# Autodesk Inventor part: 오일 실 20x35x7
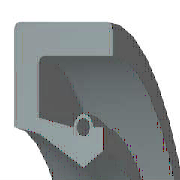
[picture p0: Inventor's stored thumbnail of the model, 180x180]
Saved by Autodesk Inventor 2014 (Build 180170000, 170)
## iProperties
IsCustomPart: 1
Created: 2012-02
Part Number: 오일 실 20x35x7
Material: 고무
Description: 회전 샤프트 립 유형 실 2 - 금속 케이스
Document SubType Name: Modeling
Standard: ISO 6194/1
Designer: mduedu
Standards Organization: ISO
Language: ko-KR
Size Designation: 20x35x7-유형 2
Categories: <MemberInstance><Categories><Category DisplayName="샤프트 부품" InternalName="7f7aeb1f-a693-4053-b835-cee3144e0d98" Mnemonic="SHFT"><Category DisplayName="실링" Intern
Density: 0.93 g/cm^3
Appearance: 고무 - 검은색 - 버전 1.1
Author: mduedu
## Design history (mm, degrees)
node "WorkPlane2"
node "WorkPoint1"
node "WorkPlane3"
body "Solid1"
node "스케치1"
revolve "회전1" stored, may be unused: angle "d37" = 360 deg
fillet "모깎기1" dims "d38" = 0.35 (= 0.05 x b)
sketch "스케치2"
  geometry: L1 (16, -0.35)-(16.8, -0.35); L2 (16, 0)-(16, -0.35); L3 (17.5, 0)-(16, 0); L4 (17.5, -7)-(17.5, 0); L5 (12.22, -7)-(17.5, -7); L6 (11.283, -4.2)-(12.22, -7); L7 (10.601, -3.72)-(11.283, -4.2); L8 (10, -1.925)-(10.601, -3.72); L9 (10.789, -1.05)-(10, -1.925); L10 (12.664, -1.05)-(10.789, -1.05); L11 (12.664, -1.925)-(12.664, -1.05); L12 (12.664, -5.6)-(12.664, -3.325); L13 (13.664, -5.6)-(12.664, -5.6); L14 (13.664, -6.3)-(13.664, -5.6); L15 (16.8, -6.3)-(13.664, -6.3); L16 (16.8, -0.35)-(16.8, -6.3); L17 (0, -15.959)-(0, 2.029); L18 (0, -15.959)-(0, 2.029); L19 (0, -19.557)-(0, 5.626) reference; L20 (-5.2, 0)-(31.2, 0) reference; A1 r 0.7 centre (12.664, -2.625) between (12.664, -3.325) and (12.664, -1.925)
  constraints: 36 end point, 7 vertical, 6 horizontal, 2 collinear, 2 point on circle, 1 centre point, 1 parallel, 1 point on line
  dimensions: "d2" = 0.35 distance of L2.start L1.start (= 0.05 x b); "d4" = 7 distance of L4.start L3.start (= b); "d6" = 0.7 horizontal distance of L1.end L3.start (= 0.1 x b); "d8" = 0.7 horizontal distance of L15.start L4.start (= 0.1 x b); "d10" = 0.7 distance of L14.start L13.start (= 0.1 x b); "d12" = 0.7 vertical distance of L1.end L10.start (= 0.1 x b); "d14" = 0.875 distance of L11.start L10.start (= 0.125 x b); "d16" = 0.7 radius of A1 (= 0.1 x b); "d18" = 0 horizontal distance of A1.centre L12.end; "d20" = 0.875 vertical distance of L9.start L8.start (= 0.125 x b); "d22" = 1.79487 vertical distance of L8.start L7.start (= 0.25641 x b); "d24" = 2.8 vertical distance of L6.start L5.start (= 0.4 x b); "d26" = 1.5 distance of L3.start L2.start (= 0.1 x dd - 0.1 x Diam); "d28" = 0.78947 horizontal distance of L9.start L8.start (= 0.0526316 x dd - 0.0526316 x Diam); "d30" = 1.875 distance of L10.start L9.start (= 0.125 x dd - 0.125 x Diam); "d32" = 1 distance of L13.start L12.start (= 0.0666667 x dd - 0.0666667 x Diam); "d34" = 0.9375 horizontal distance of L6.start L5.start (= 0.0625 x dd - 0.0625 x Diam); "d36" = 0.68182 horizontal distance of L7.start L6.start (= 0.0454545 x dd - 0.0454545 x Diam); "msp_d39" = 20 diameter of L8.start L17 (= Diam); "msp_d40" = 35 diameter of L4 L17 (= dd)
other parameters: "dd" = 35 [user parameter; used in 7 equation terms], "Diam" = 20 [user parameter; used in 7 equation terms], "b" = 7 [user parameter; used in 13 equation terms], "d0" = -7 (computed from b), "d1" = 0.4 (derived), "d3" = 8 (derived), "d5" = 0.8 (derived), "d7" = 0.8 (derived), "d9" = 0.8 (derived), "d11" = 0.8 (derived), "d13" = 1 (derived), "d15" = 0.8 (derived), "d17" = 0 (derived), "d19" = 1 (derived), "d21" = 2.05128 (derived), "d23" = 3.2 (derived), "d25" = 2 (derived), "d27" = 1.05263 (derived), "d29" = 2.5 (derived), "d31" = 1.33333 (derived), "d33" = 1.25 (derived), "d35" = 0.90909 (derived), "d42" = 0
